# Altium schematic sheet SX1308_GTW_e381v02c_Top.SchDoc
size B; DocumentNumber: 5; SheetNumber: 5; SheetTotal: 5
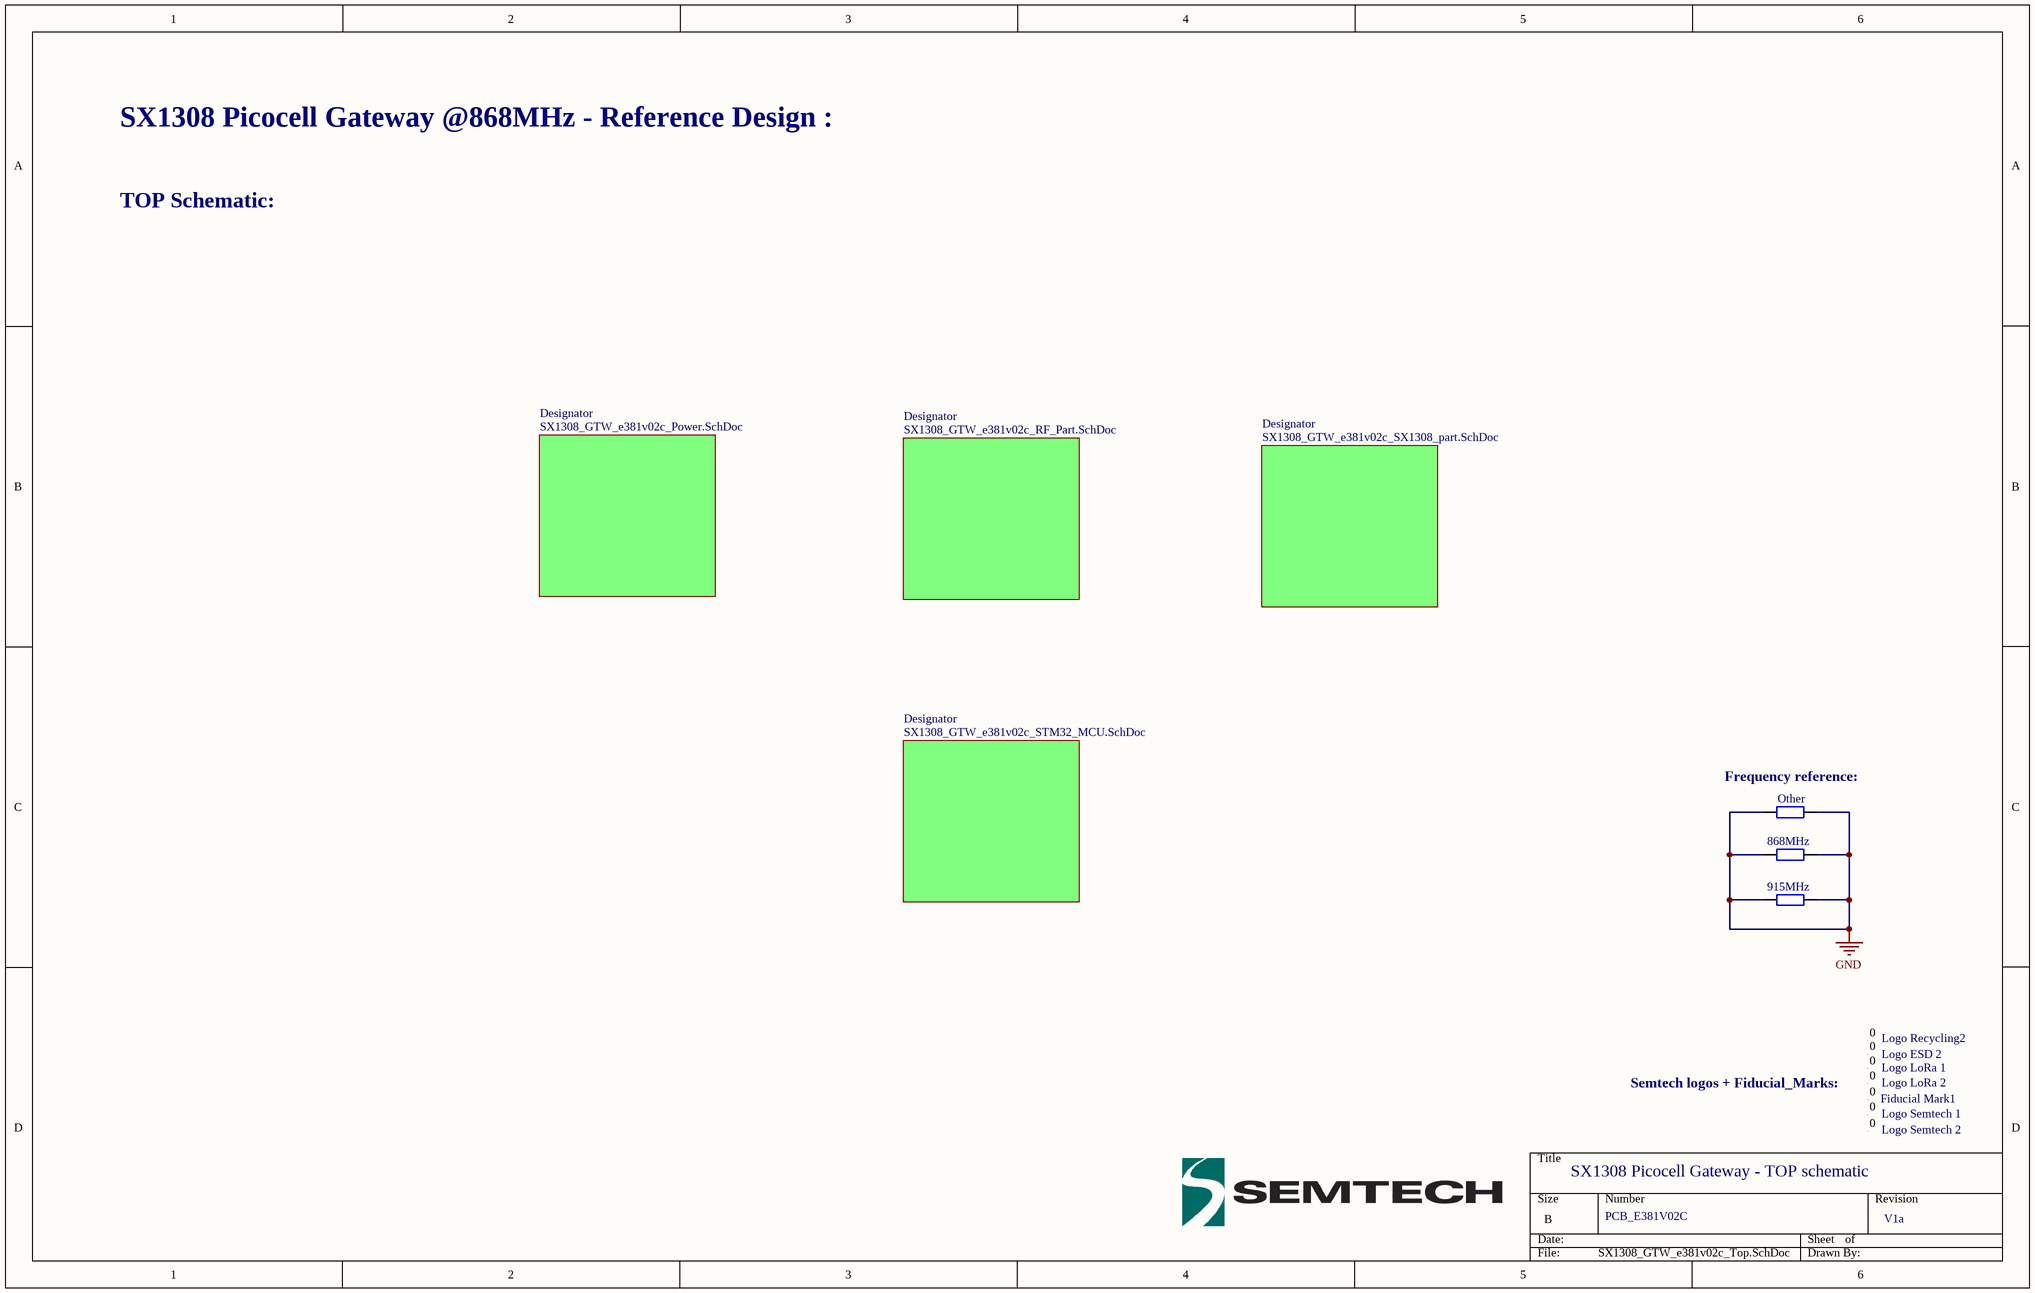
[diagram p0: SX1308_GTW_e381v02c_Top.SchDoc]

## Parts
868MHz  Resistor  [rlc_402_smd]  (value not drawn)
915MHz  Resistor  [rlc_402_smd]  (value not drawn)
Fiducial_Mark1  Logo symbol  BOT  [fiducial_mark_signal_top]  (value not drawn)
Logo_ESD_2  Logo symbol  [Logo ESD]  (value not drawn)
Logo_LoRa_1  Logo symbol TOP  [Logo LoRa Size3]  (value not drawn)
Logo_LoRa_2  Logo symbol TOP  [Logo LoRa Size3]  (value not drawn)
Logo_Recycling2  Logo symbol  [Logo Recycling1]  (value not drawn)
Logo_Semtech_1  Logo symbol TOP  [logo_semtech_horiz_size3]  (value not drawn)
Logo_Semtech_2  Logo Semtech  Bot2  [logo_semtech_horiz_size2]  (value not drawn)
Other  Resistor  [rlc_402_smd]  (value not drawn)

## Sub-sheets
Designator = SX1308_GTW_e381v02c_Power.SchDoc: no entries
Designator = SX1308_GTW_e381v02c_SX1308_part.SchDoc: no entries
Designator = SX1308_GTW_e381v02c_RF_Part.SchDoc: no entries
Designator = SX1308_GTW_e381v02c_STM32_MCU.SchDoc: no entries

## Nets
GND: 868MHz.1 868MHz.2 915MHz.1 915MHz.2 Other.1 Other.2

Not connected (* = marked no-connect by the designer): Fiducial_Mark1 0; Logo_ESD_2 0; Logo_LoRa_1 0; Logo_LoRa_2 0; Logo_Recycling2 0; Logo_Semtech_1 0; Logo_Semtech_2 0

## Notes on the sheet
- SX1308 Picocell Gateway @868MHz - Reference Design :
- TOP Schematic:
- (near Other) Frequency reference:
- Semtech logos + Fiducial_Marks:
- SX1308 Picocell Gateway - TOP schematic
- PCB_E381V02C
- V1a

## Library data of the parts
868MHz 915MHz Other = Resistor: Resistor SMD - IEC symbol version
Fiducial_Mark1 Logo_ESD_2 Logo_LoRa_1 Logo_LoRa_2 Logo_Recycling2 Logo_Semtech_1 Logo_Semtech_2 = Logo: Schematic symbol for Logo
